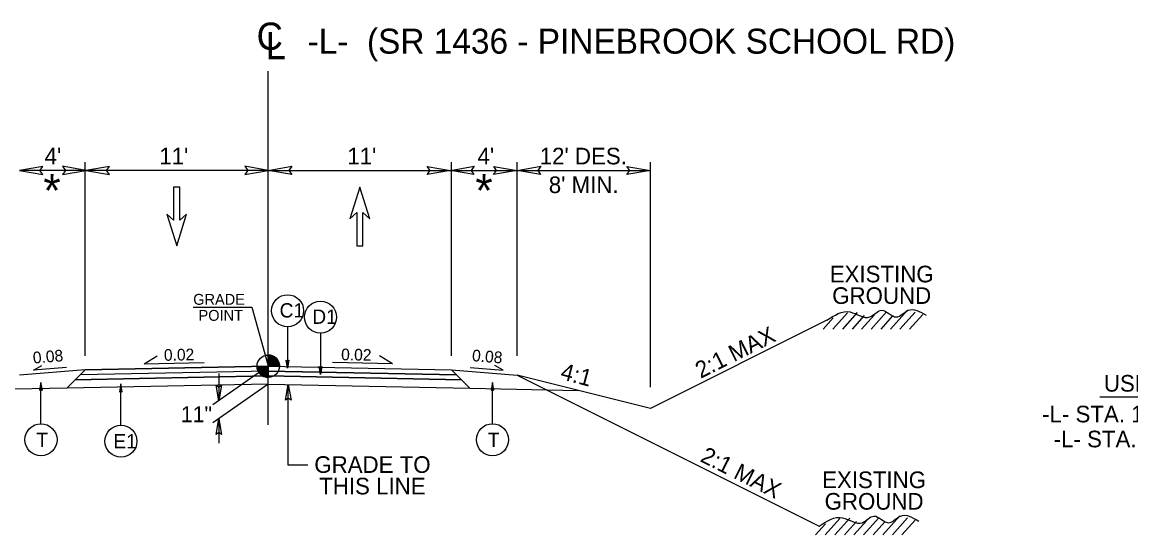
# Model space of a CAD drawing. Extents: x 1553884 to 1554215, y 810431 to 810779.
# Drawn here: x 1553946.8 to 1554013.4, y 810697.5 to 810728.3 of the extents above; entities that cross this region are included whole.
import ezdxf

# ---------------------------------------------------------------- set-up
doc = ezdxf.new("R2010")
doc.units = 0
for name, color, linetype in [('Old_Level_15', 7, 'Continuous'), ('Old_Level_20', 7, 'Continuous'), ('Prop Hatching', 7, 'Continuous'), ('Prop Shade Light', 7, 'Continuous'), ('Prop Terminator CELL', 7, 'Continuous'), ('Sheet Data Field CELL', 7, 'Continuous'), ('Sheet Sticker Exception Certification CELL', 7, 'Continuous'), ('Typical Arrow Superelevation CELL', 7, 'Continuous'), ('Typical Detail Pavement Repair CELL', 7, 'Continuous'), ('Typical Shoulder Slope CELL', 7, 'Continuous'), ('Typical Text Centerline CELL', 7, 'Continuous'), ('Typical Text ID Circle CELL', 7, 'Continuous')]:
    doc.layers.add(name, color=color, linetype=linetype)

msp = doc.modelspace()

# ---------------------------------------------------------------- linework, layer by layer
at = {"layer": 'Old_Level_15'}
for points in [[(1553948.075, 810719.628), (1553946.669, 810719.385), (1553948.083, 810719.135), (1553947.904, 810719.385)], [(1553949.263, 810719.143), (1553950.669, 810719.385), (1553949.256, 810719.635), (1553949.435, 810719.385)], [(1553952.075, 810719.628), (1553950.669, 810719.385), (1553952.083, 810719.135), (1553951.904, 810719.385)], [(1553960.212, 810719.143), (1553961.618, 810719.385), (1553960.204, 810719.635), (1553960.384, 810719.385)], [(1553963.024, 810719.143), (1553961.618, 810719.385), (1553963.032, 810719.635), (1553962.852, 810719.385)], [(1553971.16, 810719.628), (1553972.566, 810719.385), (1553971.152, 810719.135), (1553971.332, 810719.385)], [(1553973.972, 810719.143), (1553972.566, 810719.385), (1553973.98, 810719.635), (1553973.8, 810719.385)], [(1553975.16, 810719.628), (1553976.566, 810719.385), (1553975.152, 810719.135), (1553975.332, 810719.385)], [(1553977.972, 810719.143), (1553976.566, 810719.385), (1553977.98, 810719.635), (1553977.8, 810719.385)], [(1553983.16, 810719.628), (1553984.566, 810719.385), (1553983.152, 810719.135), (1553983.332, 810719.385)], [(1553962.86, 810707.974), (1553962.779, 810707.505), (1553962.696, 810707.976), (1553962.779, 810707.917)], [(1553964.836, 810707.592), (1553964.755, 810707.123), (1553964.672, 810707.594), (1553964.755, 810707.534)], [(1553948.049, 810706.177), (1553947.968, 810706.645), (1553947.885, 810706.174), (1553947.968, 810706.234)], [(1553952.852, 810706.087), (1553952.771, 810706.556), (1553952.688, 810706.084), (1553952.771, 810706.144)], [(1553975.166, 810706.177), (1553975.085, 810706.645), (1553975.002, 810706.174), (1553975.085, 810706.234)], [(1553958.81, 810706.476), (1553958.648, 810705.539), (1553958.482, 810706.481), (1553958.648, 810706.361)], [(1553962.66, 810705.574), (1553962.821, 810706.511), (1553962.988, 810705.568), (1553962.821, 810705.688)], [(1553958.487, 810703.519), (1553958.648, 810704.456), (1553958.815, 810703.514), (1553958.648, 810703.634)]]:
    msp.add_lwpolyline(points, close=True, dxfattribs=at)
at = {"layer": 'Old_Level_20'}
for p, q in [((1553961.618, 810707.618), (1553958.295, 810705.291)), ((1553961.618, 810706.535), (1553958.295, 810704.209)), ((1553958.648, 810707.171), (1553958.648, 810705.539)), ((1553958.648, 810704.456), (1553958.648, 810702.995))]:
    msp.add_line(p, q, dxfattribs=at)
at = {"layer": 'Prop Hatching'}
msp.add_line((1553961.618, 810704.086), (1553961.618, 810725.352), dxfattribs=at)
for points in [[(1553956.711, 810716.76), (1553956.305, 810716.385), (1553956.305, 810718.385), (1553955.93, 810718.385), (1553955.93, 810716.385), (1553955.524, 810716.76), (1553956.118, 810714.854)], [(1553966.524, 810716.479), (1553966.93, 810716.854), (1553966.93, 810714.854), (1553967.305, 810714.854), (1553967.305, 810716.854), (1553967.711, 810716.479), (1553967.118, 810718.385)]]:
    msp.add_lwpolyline(points, close=True, dxfattribs=at)
at = {"layer": 'Prop Shade Light'}
for p, q in [((1553950.618, 810707.398), (1553949.512, 810706.293)), ((1553961.618, 810707.323), (1553950.317, 810707.097)), ((1553961.618, 810707.618), (1553950.618, 810707.398)), ((1553961.618, 810707.618), (1553972.618, 810707.398)), ((1553961.618, 810707.323), (1553972.919, 810707.097)), ((1553972.618, 810707.398), (1553973.723, 810706.293)), ((1553961.618, 810706.535), (1553949.512, 810706.293)), ((1553961.618, 810707.035), (1553950.023, 810706.803)), ((1553961.618, 810707.035), (1553973.213, 810706.803)), ((1553961.618, 810706.535), (1553973.723, 810706.293))]:
    msp.add_line(p, q, dxfattribs=at)
for points in [[(1553961.618, 810707.323), (1553950.317, 810707.097), (1553950.023, 810706.803), (1553961.618, 810707.035)], [(1553961.618, 810707.323), (1553972.919, 810707.097), (1553973.213, 810706.803), (1553961.618, 810707.035)]]:
    msp.add_lwpolyline(points, close=True, dxfattribs=at)
at = {"layer": 'Prop Terminator CELL'}
msp.add_lwpolyline([(1553972.618, 810707.398), (1553972.919, 810707.097), (1553961.618, 810707.323), (1553950.317, 810707.097), (1553950.618, 810707.398), (1553961.618, 810707.618)], close=True, dxfattribs=at)
at = {"layer": 'Sheet Data Field CELL'}
for p, q in [((1553961.618, 810707.618), (1553961.618, 810708.29)), ((1553960.946, 810707.618), (1553961.618, 810707.618)), ((1553961.616, 810706.947), (1553961.618, 810707.618)), ((1553961.618, 810707.618), (1553961.616, 810706.947)), ((1553962.289, 810707.618), (1553961.618, 810707.618))]:
    msp.add_line(p, q, dxfattribs=at)
for points in [[(1553961.624, 810708.29), (1553961.624, 810708.29), (1553961.624, 810707.618)], [(1553961.637, 810708.29), (1553961.637, 810707.618)], [(1553961.651, 810708.288), (1553961.651, 810707.618)], [(1553961.664, 810708.288), (1553961.664, 810707.618)], [(1553961.678, 810708.287), (1553961.678, 810707.618)], [(1553961.691, 810708.285), (1553961.691, 810707.618)], [(1553961.704, 810708.284), (1553961.704, 810707.618)], [(1553961.718, 810708.282), (1553961.718, 810707.618)], [(1553961.731, 810708.281), (1553961.731, 810707.618)], [(1553961.745, 810708.278), (1553961.745, 810707.618)], [(1553961.758, 810708.275), (1553961.758, 810707.618)], [(1553961.772, 810708.272), (1553961.772, 810707.618)], [(1553961.785, 810708.269), (1553961.785, 810707.618)], [(1553961.798, 810708.264), (1553961.798, 810707.618)], [(1553961.812, 810708.261), (1553961.812, 810707.618)], [(1553961.825, 810708.257), (1553961.825, 810707.618)], [(1553961.839, 810708.252), (1553961.839, 810707.618)], [(1553961.852, 810708.248), (1553961.852, 810707.618)], [(1553961.866, 810708.242), (1553961.866, 810707.618)], [(1553961.879, 810708.236), (1553961.879, 810707.618)], [(1553961.892, 810708.23), (1553961.892, 810707.618)], [(1553961.906, 810708.224), (1553961.906, 810707.618)], [(1553961.919, 810708.218), (1553961.919, 810707.618)], [(1553961.933, 810708.211), (1553961.933, 810707.618)], [(1553961.946, 810708.203), (1553961.946, 810707.618)], [(1553961.96, 810708.196), (1553961.96, 810707.618)], [(1553961.973, 810708.188), (1553961.973, 810707.618)], [(1553961.986, 810708.179), (1553961.986, 810707.618)], [(1553962, 810708.17), (1553962, 810707.618)], [(1553962.013, 810708.16), (1553962.013, 810707.618)], [(1553962.027, 810708.151), (1553962.027, 810707.618)], [(1553962.04, 810708.14), (1553962.04, 810707.618)], [(1553962.054, 810708.129), (1553962.054, 810707.618)], [(1553962.067, 810708.117), (1553962.067, 810707.618)], [(1553962.08, 810708.105), (1553962.08, 810707.618)], [(1553962.094, 810708.091), (1553962.094, 810707.618)], [(1553962.107, 810708.078), (1553962.107, 810707.618)], [(1553962.121, 810708.063), (1553962.121, 810707.618)], [(1553962.134, 810708.046), (1553962.134, 810707.618)], [(1553962.148, 810708.03), (1553962.148, 810707.618)], [(1553962.161, 810708.012), (1553962.161, 810707.618)], [(1553962.174, 810707.993), (1553962.174, 810707.618)], [(1553962.188, 810707.972), (1553962.188, 810707.618)], [(1553962.201, 810707.95), (1553962.201, 810707.618)], [(1553962.215, 810707.926), (1553962.215, 810707.618)], [(1553962.228, 810707.897), (1553962.228, 810707.618)], [(1553962.242, 810707.866), (1553962.242, 810707.618)], [(1553960.95, 810707.618), (1553960.95, 810707.545)], [(1553960.963, 810707.618), (1553960.963, 810707.466)], [(1553960.976, 810707.618), (1553960.976, 810707.418)], [(1553960.99, 810707.618), (1553960.99, 810707.378)], [(1553961.003, 810707.618), (1553961.003, 810707.347)], [(1553961.017, 810707.618), (1553961.017, 810707.318)], [(1553961.03, 810707.618), (1553961.03, 810707.293)], [(1553961.043, 810707.618), (1553961.043, 810707.269)], [(1553961.057, 810707.618), (1553961.057, 810707.248)], [(1553961.07, 810707.618), (1553961.07, 810707.229)], [(1553961.084, 810707.618), (1553961.084, 810707.211)], [(1553961.097, 810707.618), (1553961.097, 810707.195)], [(1553961.111, 810707.618), (1553961.111, 810707.178)], [(1553961.124, 810707.618), (1553961.124, 810707.163)], [(1553961.137, 810707.618), (1553961.137, 810707.148)], [(1553961.151, 810707.618), (1553961.151, 810707.135)], [(1553961.164, 810707.618), (1553961.164, 810707.123)], [(1553961.178, 810707.618), (1553961.178, 810707.111)], [(1553961.191, 810707.618), (1553961.191, 810707.099)], [(1553961.205, 810707.618), (1553961.205, 810707.089)], [(1553961.218, 810707.618), (1553961.218, 810707.078)], [(1553961.231, 810707.618), (1553961.231, 810707.069)], [(1553961.245, 810707.618), (1553961.245, 810707.06)], [(1553961.258, 810707.618), (1553961.258, 810707.051)], [(1553961.272, 810707.618), (1553961.272, 810707.042)], [(1553961.285, 810707.618), (1553961.285, 810707.035)], [(1553961.299, 810707.618), (1553961.299, 810707.028)], [(1553961.312, 810707.618), (1553961.312, 810707.02)], [(1553961.325, 810707.618), (1553961.325, 810707.014)], [(1553961.339, 810707.618), (1553961.339, 810707.008)], [(1553961.352, 810707.618), (1553961.352, 810707.002)], [(1553961.366, 810707.618), (1553961.366, 810706.996)], [(1553961.379, 810707.618), (1553961.379, 810706.99)], [(1553961.393, 810707.618), (1553961.393, 810706.986)], [(1553961.406, 810707.618), (1553961.406, 810706.981)], [(1553961.419, 810707.618), (1553961.419, 810706.977)], [(1553961.433, 810707.618), (1553961.433, 810706.974)], [(1553961.446, 810707.618), (1553961.446, 810706.969)], [(1553961.46, 810707.618), (1553961.46, 810706.966)], [(1553961.473, 810707.618), (1553961.473, 810706.963)], [(1553961.487, 810707.618), (1553961.487, 810706.96)], [(1553961.5, 810707.618), (1553961.5, 810706.957)], [(1553961.513, 810707.618), (1553961.513, 810706.956)], [(1553961.527, 810707.618), (1553961.527, 810706.953)], [(1553961.54, 810707.618), (1553961.54, 810706.951)], [(1553961.554, 810707.618), (1553961.554, 810706.95)], [(1553961.567, 810707.618), (1553961.567, 810706.948)], [(1553961.581, 810707.618), (1553961.581, 810706.948)], [(1553961.594, 810707.618), (1553961.594, 810706.947)], [(1553961.607, 810707.618), (1553961.607, 810706.947), (1553961.607, 810706.947)], [(1553962.255, 810707.829), (1553962.255, 810707.618)], [(1553962.268, 810707.782), (1553962.268, 810707.618)], [(1553962.282, 810707.714), (1553962.282, 810707.618)]]:
    msp.add_lwpolyline(points, dxfattribs=at)
msp.add_circle((1553961.617, 810707.618), 0.671, dxfattribs=at)
for start, end in [(359.99048, 89.99048), (179.99048, 269.99048)]:
    msp.add_arc((1553961.617, 810707.618), 0.671, start, end, dxfattribs=at)
at = {"layer": 'Typical Arrow Superelevation CELL'}
for p, q in [((1553954.164, 810707.762), (1553954.947, 810708.235)), ((1553969.072, 810707.762), (1553968.289, 810708.235)), ((1553954.164, 810707.762), (1553957.762, 810707.834)), ((1553969.072, 810707.762), (1553965.474, 810707.834)), ((1553962.821, 810701.68), (1553962.821, 810706.511)), ((1554011.552, 810705.771), (1554041.51, 810705.771)), ((1553963.987, 810701.68), (1553962.821, 810701.68))]:
    msp.add_line(p, q, dxfattribs=at)
for points in [[(1553949.491, 810707.538), (1553947.518, 810707.38), (1553948.019, 810707.664)], [(1553973.745, 810707.538), (1553975.717, 810707.38), (1553975.217, 810707.664)]]:
    msp.add_lwpolyline(points, dxfattribs=at)
at = {"layer": 'Typical Shoulder Slope CELL'}
for p, q in [((1553950.618, 810708.244), (1553950.618, 810719.885)), ((1553972.618, 810708.244), (1553972.618, 810719.885)), ((1553976.566, 810708.244), (1553976.566, 810719.885)), ((1553984.566, 810706.359), (1553984.566, 810719.885)), ((1553950.669, 810719.385), (1553946.669, 810719.385)), ((1553961.618, 810719.385), (1553950.669, 810719.385)), ((1553961.618, 810719.385), (1553972.566, 810719.385)), ((1553972.566, 810719.385), (1553976.566, 810719.385)), ((1553976.566, 810719.385), (1553984.566, 810719.385)), ((1553996.396, 810710.821), (1553995.521, 810709.849)), ((1553996.991, 810710.843), (1553996.097, 810709.849)), ((1553997.401, 810710.658), (1553996.673, 810709.849)), ((1553998.025, 810710.711), (1553997.249, 810709.849)), ((1553998.75, 810710.877), (1553997.825, 810709.849)), ((1553999.111, 810710.638), (1553998.401, 810709.849)), ((1553999.998, 810710.984), (1553998.977, 810709.849)), ((1554000.464, 810710.861), (1553999.553, 810709.849)), ((1554000.926, 810710.735), (1554000.129, 810709.849)), ((1553995.159, 810710.379), (1553984.566, 810705.082)), ((1553995.546, 810710.517), (1553994.945, 810709.849)), ((1553950.618, 810707.398), (1553946.669, 810707.082)), ((1553972.618, 810707.398), (1553976.566, 810707.082)), ((1553984.566, 810705.082), (1553976.566, 810707.082)), ((1553976.566, 810707.082), (1553994.702, 810698.015)), ((1553949.512, 810706.293), (1553942.989, 810706.162)), ((1553973.723, 810706.293), (1553980.246, 810706.162)), ((1553999.541, 810698.62), (1553998.52, 810697.484)), ((1553995.089, 810698.153), (1553994.488, 810697.484)), ((1553995.938, 810698.457), (1553995.064, 810697.484)), ((1553996.533, 810698.478), (1553995.64, 810697.484)), ((1553996.944, 810698.294), (1553996.216, 810697.484)), ((1553997.567, 810698.347), (1553996.792, 810697.484)), ((1553998.292, 810698.513), (1553997.368, 810697.484)), ((1553998.653, 810698.273), (1553997.944, 810697.484)), ((1554000.006, 810698.497), (1553999.096, 810697.484)), ((1554000.469, 810698.371), (1553999.672, 810697.484))]:
    msp.add_line(p, q, dxfattribs=at)
for points in [[(1553995.159, 810710.379), (1553996.554, 810710.878), (1553997.749, 810710.578), (1553998.446, 810710.977), (1553999.342, 810710.578), (1554000.039, 810710.977), (1554001.135, 810710.678)], [(1553994.702, 810698.015), (1553996.096, 810698.513), (1553997.291, 810698.214), (1553997.988, 810698.613), (1553998.885, 810698.214), (1553999.582, 810698.613), (1554000.677, 810698.314)]]:
    msp.add_spline(points, degree=3, dxfattribs=at)
at = {"layer": 'Typical Text Centerline CELL'}
msp.add_lwpolyline([(1553957.099, 810711.162), (1553960.637, 810711.162), (1553961.604, 810707.638)], dxfattribs=at)
at = {"layer": 'Typical Text ID Circle CELL'}
for p, q in [((1553962.779, 810709.991), (1553962.779, 810707.505)), ((1553964.755, 810709.608), (1553964.755, 810707.123)), ((1553947.968, 810704.16), (1553947.968, 810706.645)), ((1553952.771, 810704.07), (1553952.771, 810706.556)), ((1553975.085, 810704.16), (1553975.085, 810706.645))]:
    msp.add_line(p, q, dxfattribs=at)
for centre in [(1553962.779, 810710.952), (1553964.755, 810710.57), (1553947.968, 810703.199), (1553952.771, 810703.109), (1553975.085, 810703.199)]:
    msp.add_circle(centre, 0.962, dxfattribs=at)

# ---------------------------------------------------------------- texts
at = {"layer": 'Old_Level_20'}
msp.add_text('11"', height=0.9558, dxfattribs=at).set_placement((1553956.365, 810704.254))
at = {"layer": 'Sheet Sticker Exception Certification CELL'}
for s, p in [('GRADE', (1553957.111, 810711.31)), ('POINT', (1553957.43, 810710.347))]:
    msp.add_text(s, height=0.6525, dxfattribs=at).set_placement(p)
at = {"layer": 'Typical Arrow Superelevation CELL'}
for s, height, p in [('-L-  (SR 1436 - PINEBROOK SCHOOL RD)', 1.5, (1553963.978, 810726.401)), ("4'", 1, (1553948.185, 810719.747)), ("11'", 1, (1553955.071, 810719.747)), ("11'", 1, (1553966.362, 810719.747)), ("4'", 1, (1553974.184, 810719.747)), ("12' DES.", 1, (1553977.919, 810719.747)), ('*', 2, (1553948.111, 810717.176)), ('*', 2, (1553974.054, 810717.176)), ("8' MIN.", 1, (1553978.464, 810718.023)), ('EXISTING', 1, (1553995.335, 810712.657)), ('GROUND', 1, (1553995.484, 810711.362)), ('USE TYPICAL SECTION NO. 2 AS FOLLOWS:', 1, (1554011.799, 810706.091)), ('-L- STA. 16+20.00 TO -L- STA. 18+52.05 (BEGIN BRIDGE)', 1, (1554008.089, 810704.243)), ('-L- STA. 21+08.72 (END BRIDGE) TO -L- STA. 23+50.00', 1, (1554008.784, 810702.743)), ('GRADE TO', 1, (1553964.382, 810701.208)), ('EXISTING', 1, (1553994.877, 810700.292)), ('THIS LINE', 1, (1553964.674, 810699.914)), ('GROUND', 1, (1553995.027, 810698.998))]:
    msp.add_text(s, height=height, dxfattribs=at).set_placement(p)
for s, height, rotation, p in [('2:1 MAX', 1, 26.56505, (1553987.583, 810706.864)), ('0.08', 0.7, 4.57392, (1553947.508, 810707.777)), ('0.02', 0.7, 1.14587, (1553955.357, 810707.942)), ('0.02', 0.7, 358.85413, (1553965.988, 810707.98)), ('0.08', 0.7, 355.42608, (1553973.834, 810707.929)), ('4:1', 1, 345.05299, (1553979.104, 810706.862)), ('2:1 MAX', 1, 333.43495, (1553987.498, 810701.926))]:
    msp.add_text(s, height=height, rotation=rotation, dxfattribs=at).set_placement(p)
at = {"layer": 'Typical Detail Pavement Repair CELL'}
for s, height, p in [('C1', 0.8608, (1553962.297, 810710.546)), ('D1', 0.8608, (1553964.26, 810710.164)), ('T', 0.861, (1553947.685, 810702.768)), ('E1', 0.8608, (1553952.315, 810702.678)), ('T', 0.861, (1553974.802, 810702.768))]:
    msp.add_text(s, height=height, dxfattribs=at).set_placement(p)
at = {"layer": 'Typical Text Centerline CELL'}
msp.add_text('C', height=1.64, dxfattribs=at).set_placement((1553960.915, 810726.63))
msp.add_text('L', height=1.641, rotation=359.9469, dxfattribs=at).set_placement((1553961.461, 810726.07))

doc.saveas('drawing.dxf')
